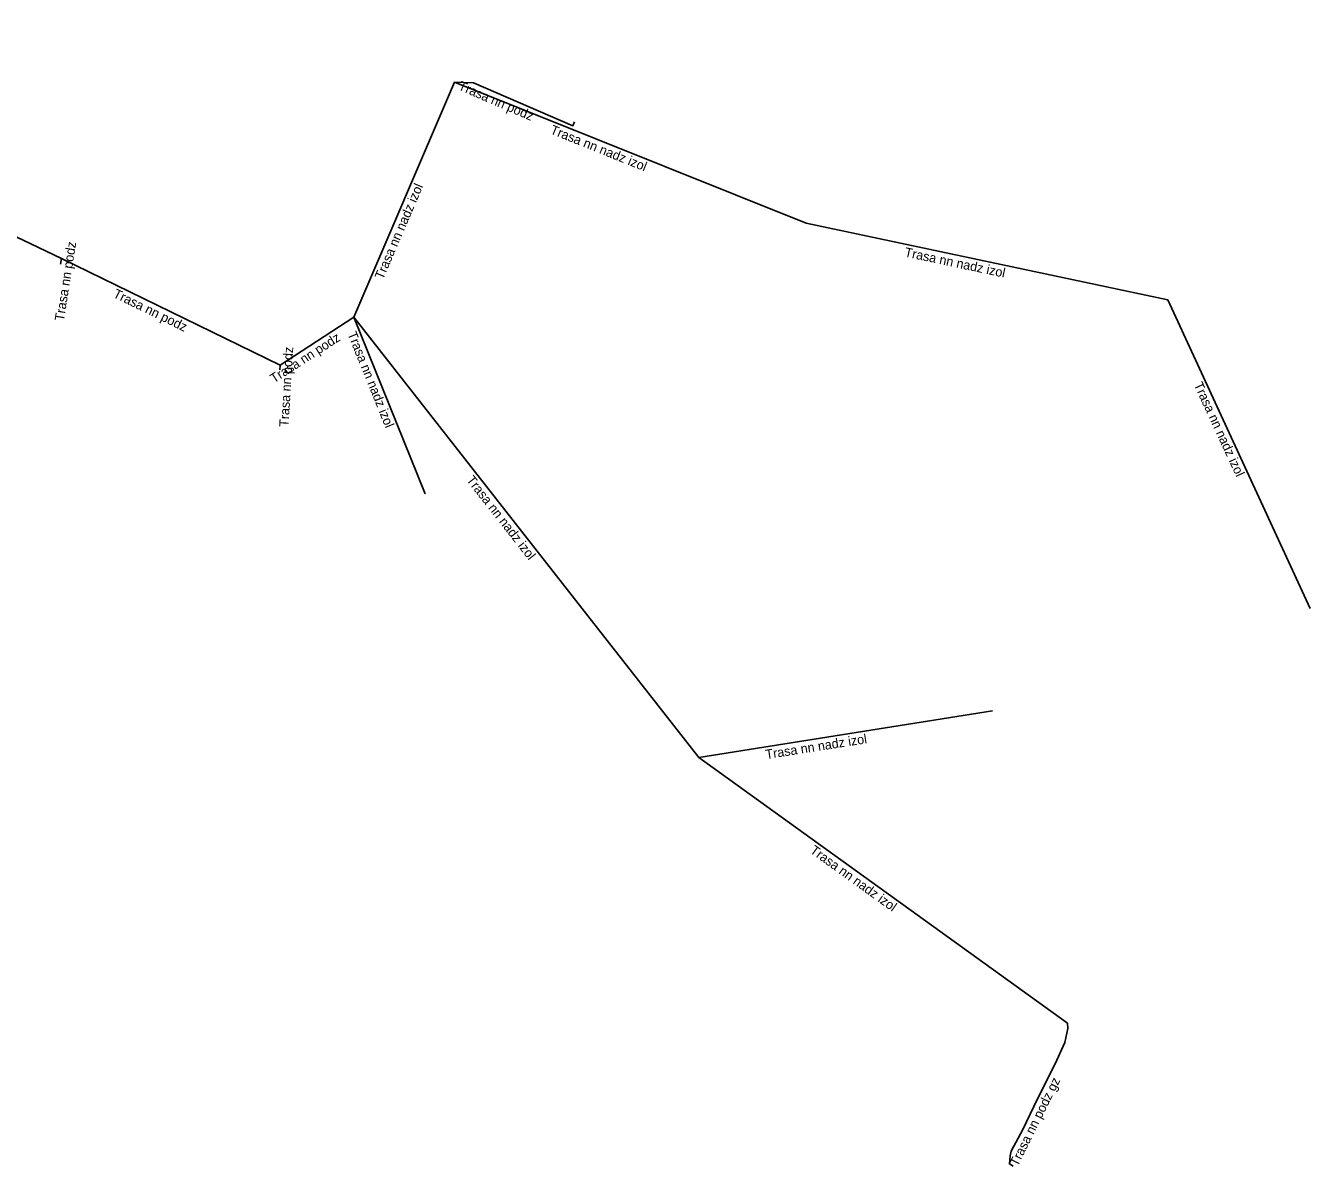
# Model space of a CAD drawing. Extents: x -681013 to -679916, y -1058385 to -1057701.
# Drawn here: x -680879.1 to -680810.6, y -1057892.4 to -1057831.6 of the extents above; entities that cross this region are included whole.
import ezdxf

# ---------------------------------------------------------------- set-up
doc = ezdxf.new("R2010")
doc.units = 0
doc.layers.add('Popiskový text - Ostatní atributy Trasy', color=7, linetype='Continuous')
doc.layers.add('Spojnice NN', color=7, linetype='Continuous')

msp = doc.modelspace()

# ---------------------------------------------------------------- linework, layer by layer
at = {"layer": 'Spojnice NN'}
for points in [[(-680903.182, -1057831.55), (-680877.216, -1057843.96)], [(-680856.24, -1057834.56), (-680861.62, -1057847.1)], [(-680849.842, -1057836.681), (-680849.928, -1057836.889), (-680855.23, -1057834.605), (-680856.24, -1057834.56)], [(-680856.24, -1057834.56), (-680837.49, -1057842.083)], [(-680837.49, -1057842.083), (-680818.19, -1057846.176)], [(-680877.216, -1057843.96), (-680877.264, -1057844.265)], [(-680877.216, -1057843.96), (-680865.556, -1057849.649)], [(-680818.19, -1057846.176), (-680810.595, -1057862.636)], [(-680865.556, -1057849.649), (-680861.62, -1057847.1)], [(-680861.62, -1057847.1), (-680857.815, -1057856.512)], [(-680861.62, -1057847.1), (-680843.221, -1057870.579)], [(-680865.556, -1057849.649), (-680865.571, -1057849.898)], [(-680843.221, -1057870.579), (-680827.543, -1057868.096)], [(-680843.221, -1057870.579), (-680823.54, -1057884.75)], [(-680826.44, -1057892.38), (-680826.65, -1057892.25), (-680826.6, -1057891.83), (-680826.55, -1057891.58), (-680825.93, -1057890.42), (-680825.14, -1057888.79), (-680824.21, -1057886.91), (-680823.69, -1057885.77), (-680823.53, -1057885.03), (-680823.54, -1057884.75)]]:
    msp.add_lwpolyline(points, dxfattribs=at)

# ---------------------------------------------------------------- texts
at = {"layer": 'Popiskový text - Ostatní atributy Trasy'}
for s, rotation, p in [('Trasa nn podz', 336.69455, (-680856.088, -1057834.943)), ('Trasa nn nadz izol', 338.13803, (-680851.181, -1057837.29)), ('Trasa nn nadz izol', 66.77936, (-680860.063, -1057845.121)), ('Trasa nn podz', 81.05632, (-680877.087, -1057847.323)), ('Trasa nn nadz izol', 348.02654, (-680832.269, -1057843.855)), ('Trasa nn podz', 333.99191, (-680874.5, -1057846.008)), ('Trasa nn podz', 32.92757, (-680865.877, -1057850.631)), ('Trasa nn nadz izol', 292.01206, (-680861.965, -1057847.98)), ('Trasa nn podz', 86.55261, (-680865.104, -1057852.955)), ('Trasa nn nadz izol', 294.76962, (-680816.822, -1057850.693)), ('Trasa nn nadz izol', 308.08354, (-680855.639, -1057855.785)), ('Trasa nn nadz izol', 8.99946, (-680839.616, -1057870.667)), ('Trasa nn nadz izol', 324.24481, (-680837.322, -1057875.627)), ('Trasa nn podz gz', 63.67928, (-680826.209, -1057892.418))]:
    msp.add_text(s, height=0.5, rotation=rotation, dxfattribs=at).set_placement(p)

doc.saveas('drawing.dxf')
